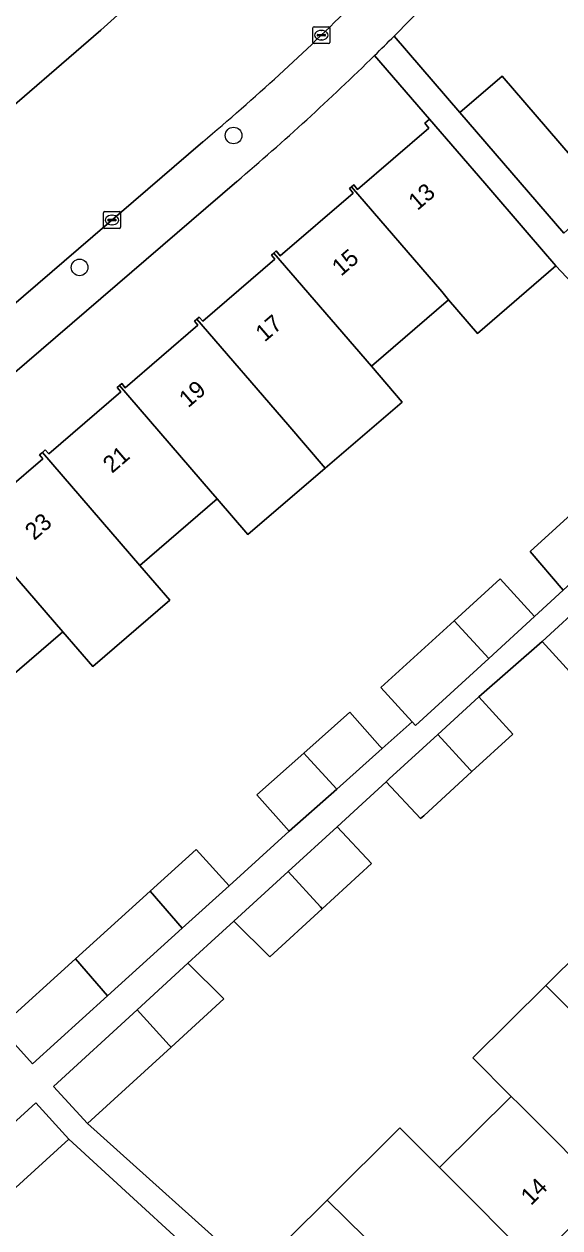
# Model space of a CAD drawing. Extents: x 159217 to 160349, y 381246 to 382172.
# Drawn here: x 160054.9 to 160086.5, y 381881.2 to 381952.3 of the extents above; entities that cross this region are included whole.
import ezdxf

# ---------------------------------------------------------------- set-up
doc = ezdxf.new("R2010")
doc.units = 0
for name, color, linetype in [('IMGEO_Boom', 7, 'Continuous'), ('IMGEO_Erf', 7, 'Continuous'), ('IMGEO_Kolk', 7, 'Continuous'), ('IMGEO_Pand', 7, 'Continuous'), ('IMGEO_Pand_nummerreeks', 7, 'Continuous'), ('IMGEO_Rijbaan_lokaal_open', 7, 'Continuous'), ('IMGEO_Voetpad_open', 7, 'Continuous')]:
    doc.layers.add(name, color=color, linetype=linetype)

msp = doc.modelspace()

# ---------------------------------------------------------------- linework, layer by layer
at = {"layer": 'IMGEO_Boom'}
for centre in [(160067.255, 381945.714), (160058.173, 381937.927)]:
    msp.add_circle(centre, 0.489, dxfattribs=at)
at = {"layer": 'IMGEO_Erf'}
for points in [[(160078.646, 381953.532), (160076.728, 381951.58), (160080.607, 381947.075), (160083.102, 381949.222), (160089.186, 381942.153)], [(160065.155, 381934.513), (160064.952, 381934.749), (160065.093, 381934.871), (160065.235, 381934.993), (160065.44, 381934.755), (160069.693, 381938.415), (160069.484, 381938.657), (160069.622, 381938.775), (160069.762, 381938.896), (160070.006, 381938.612), (160074.31, 381942.317), (160074.086, 381942.577), (160074.212, 381942.685), (160074.341, 381942.796), (160074.567, 381942.534), (160078.776, 381946.156), (160078.533, 381946.438), (160078.813, 381946.68), (160075.577, 381950.44)], [(160067.439, 381942.998), (160034.634, 381914.758)], [(160094.493, 381929.287), (160086.272, 381938.014), (160081.638, 381934.026), (160079.936, 381936.003), (160075.386, 381932.088), (160077.2, 381929.98), (160072.667, 381926.079), (160068.104, 381922.152), (160066.291, 381924.259), (160061.729, 381920.333), (160063.494, 381918.286), (160058.946, 381914.371), (160057.181, 381916.418), (160052.615, 381912.488)], [(160051.783, 381923.003), (160055.997, 381926.63), (160055.803, 381926.855), (160055.977, 381927.005), (160056.151, 381927.155), (160056.35, 381926.924), (160060.604, 381930.586), (160060.388, 381930.837), (160060.522, 381930.952), (160060.657, 381931.068), (160060.868, 381930.823), (160065.155, 381934.513)], [(160053.451, 381893.049), (160057.928, 381897.108), (160062.339, 381901.108), (160065.05, 381903.566), (160066.991, 381901.425), (160070.545, 381904.636), (160068.633, 381906.783), (160071.407, 381909.255), (160074.115, 381911.666), (160075.89, 381909.673), (160076.027, 381909.519), (160077.792, 381911.092), (160075.943, 381913.117), (160080.278, 381917.066), (160082.985, 381919.532), (160085.004, 381917.316), (160086.7, 381918.87), (160084.756, 381921.146), (160089.146, 381925.146)], [(160087.49, 381913.626), (160085.456, 381915.833), (160081.724, 381912.575), (160083.737, 381910.379), (160081.319, 381908.162), (160078.475, 381905.555), (160078.288, 381905.384), (160076.25, 381907.558), (160074.834, 381906.26), (160073.359, 381904.908), (160075.397, 381902.734), (160072.487, 381900.067), (160069.394, 381897.231), (160067.273, 381899.329), (160065.935, 381898.103), (160064.56, 381896.843), (160066.682, 381894.745), (160063.581, 381891.903), (160058.644, 381887.378), (160068.442, 381878.563), (160072.772, 381882.869), (160077.063, 381887.136), (160079.405, 381884.78), (160083.635, 381888.986), (160081.376, 381891.256), (160085.686, 381895.543), (160089.935, 381899.769)], [(160067.787, 381877.048), (160057.544, 381886.458), (160053.532, 381882.802), (160051.489, 381884.866), (160049.953, 381883.467), (160051.997, 381881.402), (160049.055, 381878.721)]]:
    msp.add_lwpolyline(points, dxfattribs=at)
msp.add_arc((159964.554, 382063.676), 158.583, 310.44959, 314.4347, dxfattribs=at)
at = {"layer": 'IMGEO_Kolk'}
for p, q in [((160071.934, 381951.212), (160071.934, 381952.064)), ((160072.009, 381952.138), (160072.861, 381952.138)), ((160072.193, 381951.632), (160072.193, 381951.644)), ((160072.236, 381951.681), (160072.634, 381951.681)), ((160072.422, 381951.918), (160072.447, 381951.918)), ((160072.677, 381951.644), (160072.677, 381951.632)), ((160072.935, 381952.064), (160072.935, 381951.212)), ((160072.861, 381951.138), (160072.009, 381951.138)), ((160072.631, 381951.595), (160072.233, 381951.595)), ((160072.445, 381951.358), (160072.42, 381951.358)), ((160059.58, 381940.296), (160059.58, 381941.148)), ((160059.655, 381941.222), (160060.507, 381941.222)), ((160060.068, 381941.002), (160060.093, 381941.002)), ((160060.581, 381941.148), (160060.581, 381940.296)), ((160059.839, 381940.716), (160059.839, 381940.728)), ((160060.277, 381940.679), (160059.879, 381940.679)), ((160059.882, 381940.765), (160060.28, 381940.765)), ((160060.091, 381940.442), (160060.066, 381940.442)), ((160060.323, 381940.728), (160060.323, 381940.716)), ((160060.507, 381940.222), (160059.655, 381940.222))]:
    msp.add_line(p, q, dxfattribs=at)
for points in [[(160071.934, 381951.212), (160071.934, 381952.064)], [(160072.009, 381952.138), (160072.861, 381952.138)], [(160072.935, 381952.064), (160072.935, 381951.212)], [(160072.861, 381951.138), (160072.009, 381951.138)], [(160059.58, 381940.296), (160059.58, 381941.148)], [(160059.655, 381941.222), (160060.507, 381941.222)], [(160060.581, 381941.148), (160060.581, 381940.296)], [(160060.507, 381940.222), (160059.655, 381940.222)]]:
    msp.add_lwpolyline(points, dxfattribs=at)
for centre, radius, start, end in [((160072.011, 381952.062), 0.0765, 91.55205, 178.44795), ((160072.011, 381952.062), 0.0765, 91.55205, 178.44795), ((160072.233, 381951.641), 0.0403, 85.87752, 175.75265), ((160072.23, 381951.631), 0.0366, 178.93798, 274.71019), ((160072.634, 381951.638), 0.043, 264.86636, 352.45326), ((160072.638, 381951.643), 0.0386, 1.73085, 96.63898), ((160072.859, 381952.062), 0.0765, 1.55205, 88.44795), ((160072.859, 381952.062), 0.0765, 1.55205, 88.44795), ((160072.011, 381951.214), 0.0765, 181.55205, 268.44795), ((160072.011, 381951.214), 0.0765, 181.55205, 268.44795), ((160072.859, 381951.214), 0.0765, 271.55205, 358.44795), ((160072.859, 381951.214), 0.0765, 271.55205, 358.44795), ((160059.657, 381941.146), 0.0765, 91.55205, 178.44795), ((160059.657, 381941.146), 0.0765, 91.55205, 178.44795), ((160060.505, 381941.146), 0.0765, 1.55205, 88.44795), ((160060.505, 381941.146), 0.0765, 1.55205, 88.44795), ((160059.657, 381940.298), 0.0765, 181.55205, 268.44795), ((160059.657, 381940.298), 0.0765, 181.55205, 268.44795), ((160059.879, 381940.725), 0.0403, 85.87752, 175.75265), ((160059.876, 381940.715), 0.0366, 178.93798, 274.71019), ((160060.28, 381940.722), 0.043, 264.86636, 352.45326), ((160060.284, 381940.727), 0.0386, 1.73085, 96.63898), ((160060.505, 381940.298), 0.0765, 271.55205, 358.44795), ((160060.505, 381940.298), 0.0765, 271.55205, 358.44795)]:
    msp.add_arc(centre, radius, start, end, dxfattribs=at)
for centre, major_axis, ratio, start_param, end_param in [((160072.421, 381951.638), (-0.387, 0.002), 0.722429, 4.712389, 7.853982), ((160072.446, 381951.638), (-0.39, 0.002), 0.717154, 1.570796, 4.712389), ((160060.067, 381940.722), (-0.387, 0.002), 0.722429, 4.712389, 7.853982), ((160060.092, 381940.722), (-0.39, 0.002), 0.717154, 1.570796, 4.712389)]:
    msp.add_ellipse(centre, major_axis=major_axis, ratio=ratio, start_param=start_param, end_param=end_param, dxfattribs=at)
at = {"layer": 'IMGEO_Pand'}
for points in [[(160086.741, 381939.951), (160088.759, 381941.785), (160089.186, 381942.153), (160083.102, 381949.222), (160080.607, 381947.075)], [(160074.212, 381942.685), (160079.546, 381936.497), (160079.936, 381936.003), (160081.638, 381934.026), (160086.272, 381938.014), (160084.57, 381939.992), (160082.075, 381942.891), (160078.813, 381946.68), (160078.533, 381946.438), (160078.776, 381946.156), (160074.567, 381942.534), (160074.341, 381942.796)], [(160069.622, 381938.775), (160075.386, 381932.088), (160079.936, 381936.003), (160079.546, 381936.497), (160074.212, 381942.685), (160074.086, 381942.577), (160074.31, 381942.317), (160070.006, 381938.612), (160069.762, 381938.896)], [(160069.622, 381938.775), (160069.484, 381938.657), (160069.693, 381938.415), (160065.44, 381934.755), (160065.235, 381934.993), (160065.093, 381934.871), (160070.45, 381928.656), (160072.667, 381926.079), (160077.2, 381929.98), (160075.386, 381932.088)], [(160060.522, 381930.952), (160065.89, 381924.725), (160066.291, 381924.259), (160068.104, 381922.152), (160072.667, 381926.079), (160070.45, 381928.656), (160065.093, 381934.871), (160064.952, 381934.749), (160065.155, 381934.513), (160060.868, 381930.823), (160060.657, 381931.068)], [(160061.729, 381920.333), (160066.291, 381924.259), (160065.89, 381924.725), (160060.522, 381930.952), (160060.388, 381930.837), (160060.604, 381930.586), (160056.35, 381926.924), (160056.151, 381927.155), (160055.977, 381927.005)], [(160055.977, 381927.005), (160055.803, 381926.855), (160055.997, 381926.63), (160051.783, 381923.003), (160051.57, 381923.25), (160051.41, 381923.112), (160057.181, 381916.418), (160058.946, 381914.371), (160063.494, 381918.286), (160061.729, 381920.333)], [(160091.155, 381922.95), (160089.146, 381925.146), (160084.756, 381921.146), (160086.7, 381918.87)], [(160057.181, 381916.418), (160051.41, 381923.112), (160051.248, 381922.973), (160051.475, 381922.709), (160047.206, 381919.035), (160046.986, 381919.29), (160046.852, 381919.175), (160052.615, 381912.488)], [(160082.985, 381919.532), (160080.278, 381917.066), (160082.305, 381914.845), (160085.004, 381917.316)], [(160088.121, 381918.289), (160085.456, 381915.833), (160087.49, 381913.626), (160090.163, 381916.089), (160089.958, 381916.285)], [(160082.305, 381914.845), (160080.278, 381917.066), (160075.943, 381913.117), (160077.792, 381911.092), (160077.981, 381910.885)], [(160079.3, 381910.354), (160081.209, 381908.27), (160081.319, 381908.162), (160083.737, 381910.379), (160081.724, 381912.575)], [(160076.027, 381909.519), (160075.89, 381909.673), (160074.115, 381911.666), (160071.407, 381909.255), (160071.586, 381909.05), (160073.341, 381907.127)], [(160081.319, 381908.162), (160081.209, 381908.27), (160079.3, 381910.354), (160076.437, 381907.729), (160076.25, 381907.558), (160078.288, 381905.384), (160078.475, 381905.555)], [(160071.407, 381909.255), (160068.633, 381906.783), (160070.545, 381904.636), (160073.341, 381907.127), (160071.586, 381909.05)], [(160073.359, 381904.908), (160070.469, 381902.259), (160072.375, 381900.178), (160072.487, 381900.067), (160075.397, 381902.734)], [(160064.218, 381898.911), (160066.991, 381901.425), (160065.05, 381903.566), (160062.339, 381901.108)], [(160072.487, 381900.067), (160072.375, 381900.178), (160070.469, 381902.259), (160067.273, 381899.329), (160069.394, 381897.231)], [(160057.928, 381897.108), (160059.815, 381894.919), (160064.218, 381898.911), (160062.339, 381901.108)], [(160098.065, 381891.598), (160092.194, 381897.497), (160089.935, 381899.769), (160085.686, 381895.543), (160087.945, 381893.272), (160093.781, 381887.407), (160093.883, 381887.508), (160093.612, 381887.78), (160097.631, 381891.776), (160097.936, 381891.469)], [(160057.928, 381897.108), (160053.451, 381893.049), (160055.391, 381890.908), (160059.815, 381894.919)], [(160064.56, 381896.843), (160061.562, 381894.095), (160063.466, 381892.017), (160063.581, 381891.903), (160066.682, 381894.745)], [(160085.686, 381895.543), (160081.376, 381891.256), (160083.635, 381888.986), (160084.117, 381888.501), (160089.462, 381883.13), (160089.565, 381883.232), (160089.331, 381883.467), (160093.435, 381887.547), (160093.677, 381887.304), (160093.781, 381887.407), (160087.945, 381893.272)], [(160061.562, 381894.095), (160056.631, 381889.575), (160058.644, 381887.378), (160063.581, 381891.903), (160063.466, 381892.017)], [(160051.489, 381884.866), (160053.532, 381882.802), (160057.544, 381886.458), (160055.589, 381888.603)], [(160083.635, 381888.986), (160079.405, 381884.78), (160085.261, 381878.896), (160085.388, 381879.022), (160085.132, 381879.279), (160089.133, 381883.258), (160089.361, 381883.029), (160089.462, 381883.13), (160084.117, 381888.501)], [(160072.772, 381882.869), (160075.034, 381880.645), (160080.982, 381874.668), (160081.113, 381874.798), (160080.864, 381875.048), (160084.875, 381879.036), (160085.137, 381878.772), (160085.261, 381878.896), (160079.405, 381884.78), (160077.063, 381887.136)], [(160075.034, 381880.645), (160072.772, 381882.869), (160068.442, 381878.563), (160073.109, 381873.868), (160076.383, 381870.576), (160076.635, 381870.323), (160076.867, 381870.553), (160076.603, 381870.819), (160080.596, 381874.79), (160080.849, 381874.536), (160080.982, 381874.668)]]:
    msp.add_lwpolyline(points, close=True, dxfattribs=at)
at = {"layer": 'IMGEO_Rijbaan_lokaal_open'}
for points in [[(160074.285, 381953.452), (160077.19, 381956.435), (160079.962, 381959.45), (160080.57, 381960.131), (160073.897, 381966.186), (160072.959, 381965.169), (160072.21, 381964.39), (160072.029, 381964.202), (160068.368, 381960.235), (160066.142, 381958.062), (160061.392, 381953.701), (160059.423, 381951.93), (160052.575, 381946.033)], [(160012.675, 381899.899), (160065.438, 381945.337)]]:
    msp.add_lwpolyline(points, dxfattribs=at)
msp.add_arc((159972.704, 382055.316), 143.857, 310.13751, 314.92033, dxfattribs=at)
at = {"layer": 'IMGEO_Voetpad_open'}
for points in [[(159992.095, 381893.974), (159995.231, 381896.742), (160000, 381900.762), (160034.563, 381930.523), (160037.988, 381933.472), (160049.17, 381943.102), (160052.575, 381946.033), (160059.423, 381951.93), (160061.392, 381953.701), (160066.142, 381958.062), (160068.368, 381960.235), (160072.029, 381964.202), (160072.21, 381964.39), (160072.959, 381965.169), (160073.897, 381966.186)], [(160076.728, 381951.58), (160078.646, 381953.532)], [(160086.741, 381939.951), (160080.607, 381947.075), (160076.728, 381951.58)], [(160075.577, 381950.44), (160078.813, 381946.68), (160082.075, 381942.891), (160084.57, 381939.992), (160086.272, 381938.014), (160094.493, 381929.287), (160096.06, 381927.443), (160093.962, 381925.521), (160091.155, 381922.95), (160086.7, 381918.87), (160085.004, 381917.316), (160082.305, 381914.845), (160077.981, 381910.885), (160077.792, 381911.092), (160076.027, 381909.519), (160073.341, 381907.127), (160070.545, 381904.636), (160066.991, 381901.425), (160064.218, 381898.911), (160059.815, 381894.919), (160055.391, 381890.908), (160053.451, 381893.049)], [(160065.438, 381945.337), (160012.675, 381899.899), (160000, 381888.954), (159998.229, 381887.404), (159993.21, 381883.114), (159982.838, 381874.211), (159972.211, 381865.09), (159952.156, 381847.982), (159950.972, 381846.948)], [(159948.828, 381842.865), (159948.378, 381831.596), (159952.057, 381829.709), (159957.077, 381834.899), (159958.818, 381836.919), (159955.642, 381840.217), (159957.007, 381841.635), (159990.64, 381876.569), (159990.482, 381876.75), (159992.495, 381878.483), (160000, 381884.944), (160033.475, 381913.761), (160034.634, 381914.758), (160067.439, 381942.998)], [(160067.273, 381899.329), (160070.469, 381902.259), (160073.359, 381904.908), (160074.834, 381906.26), (160076.25, 381907.558), (160076.437, 381907.729), (160079.3, 381910.354), (160081.724, 381912.575), (160085.456, 381915.833), (160088.121, 381918.289)], [(160068.442, 381878.563), (160058.644, 381887.378), (160056.631, 381889.575), (160061.562, 381894.095), (160064.56, 381896.843), (160065.935, 381898.103), (160067.273, 381899.329)], [(160047.011, 381880.786), (160049.953, 381883.467), (160051.489, 381884.866), (160055.589, 381888.603), (160057.544, 381886.458), (160067.787, 381877.048)]]:
    msp.add_lwpolyline(points, dxfattribs=at)
for centre, radius, start, end in [((159972.704, 382055.316), 143.857, 310.13751, 314.92033), ((159982.939, 382045.123), 132.464, 314.37454, 315.07526), ((159982.939, 382045.123), 132.464, 314.37454, 315.07526), ((159964.554, 382063.676), 158.583, 310.44959, 314.4347)]:
    msp.add_arc(centre, radius, start, end, dxfattribs=at)

# ---------------------------------------------------------------- texts
at = {"layer": 'IMGEO_Pand_nummerreeks'}
for s, rotation, p in [('13', 40.7322, (160078.105, 381941.25)), ('15', 40.7322, (160073.596, 381937.367)), ('17', 40.7322, (160069.087, 381933.485)), ('19', 40.7322, (160064.578, 381929.602)), ('21', 40.7322, (160060.086, 381925.733)), ('23', 40.73157, (160055.491, 381921.776)), ('14', 44.78811, (160084.8, 381882.505))]:
    msp.add_text(s, height=1, rotation=rotation, dxfattribs=at).set_placement(p)

doc.saveas('drawing.dxf')
